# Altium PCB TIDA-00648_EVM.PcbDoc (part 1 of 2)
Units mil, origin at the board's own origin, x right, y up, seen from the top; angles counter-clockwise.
Board outline 2200 x 2000 mil, 4 copper layers (Component Side, Ground Plane, Power Plane, Solder Side), stack 55.6 mil thick; 91 components, 64 nets, 274 pads, 141 vias.
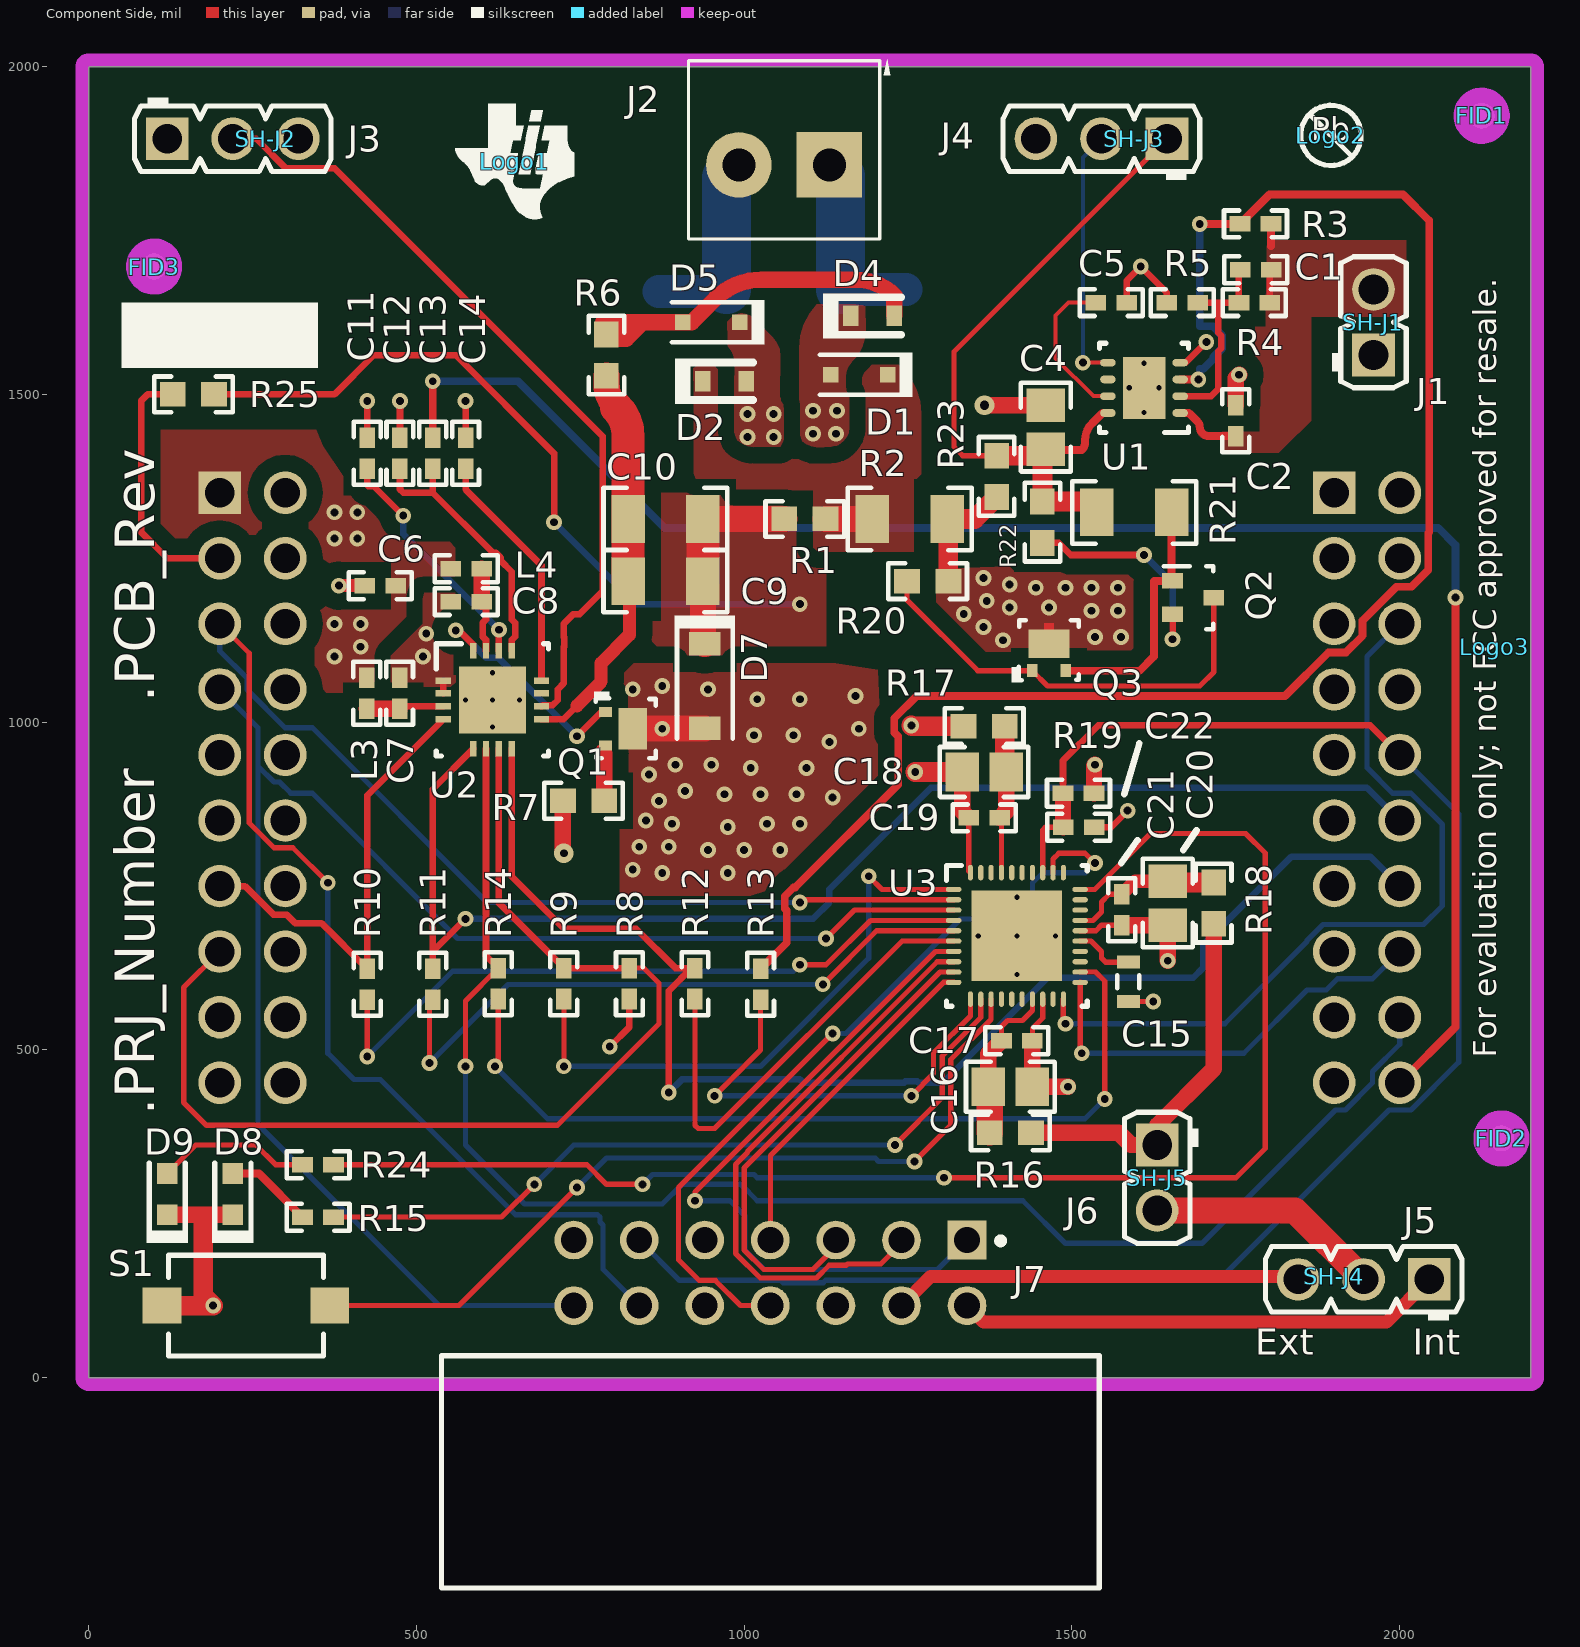
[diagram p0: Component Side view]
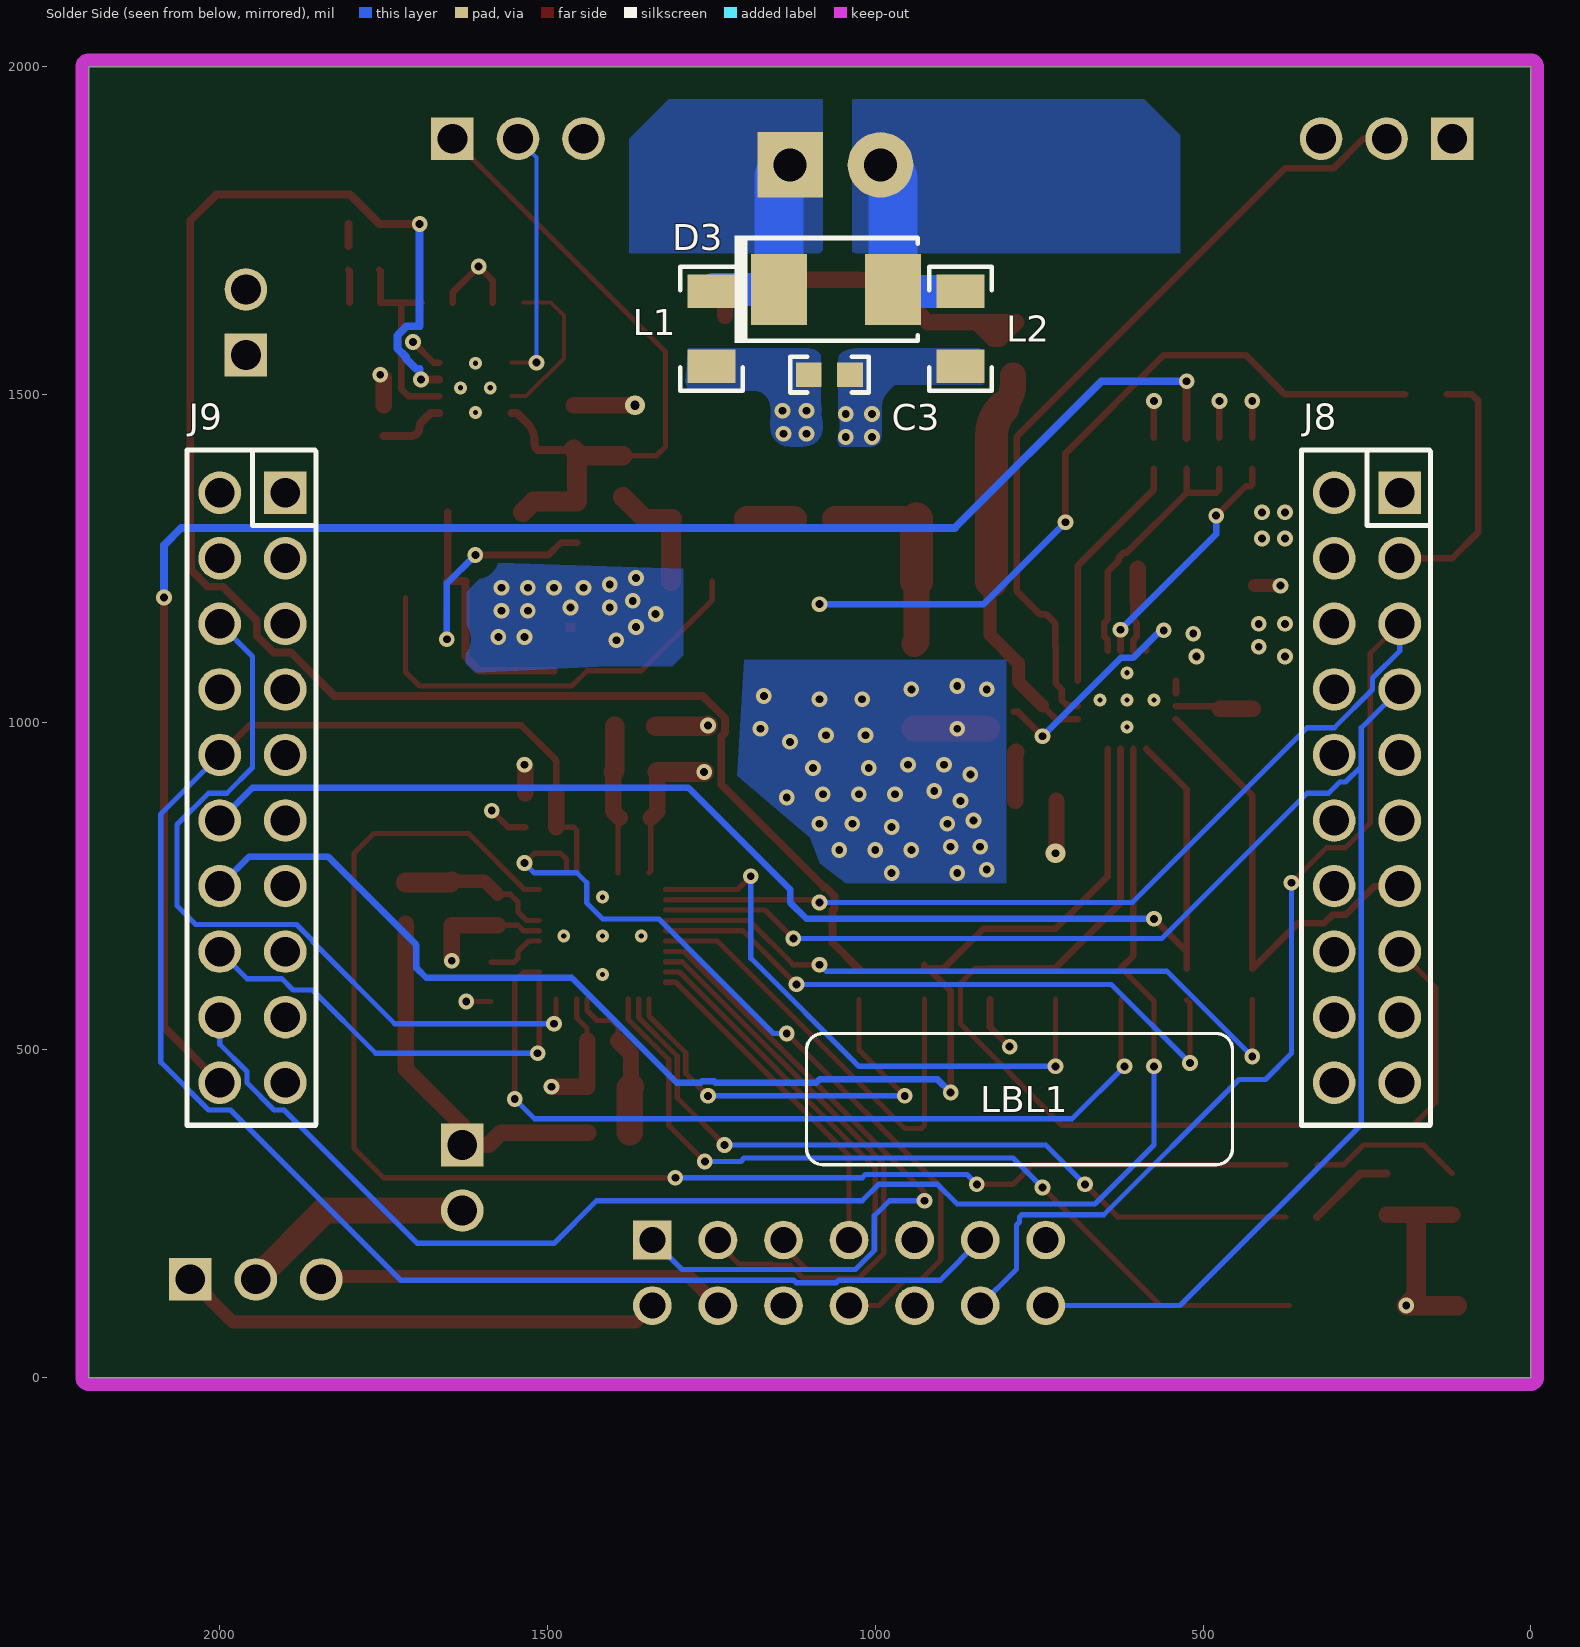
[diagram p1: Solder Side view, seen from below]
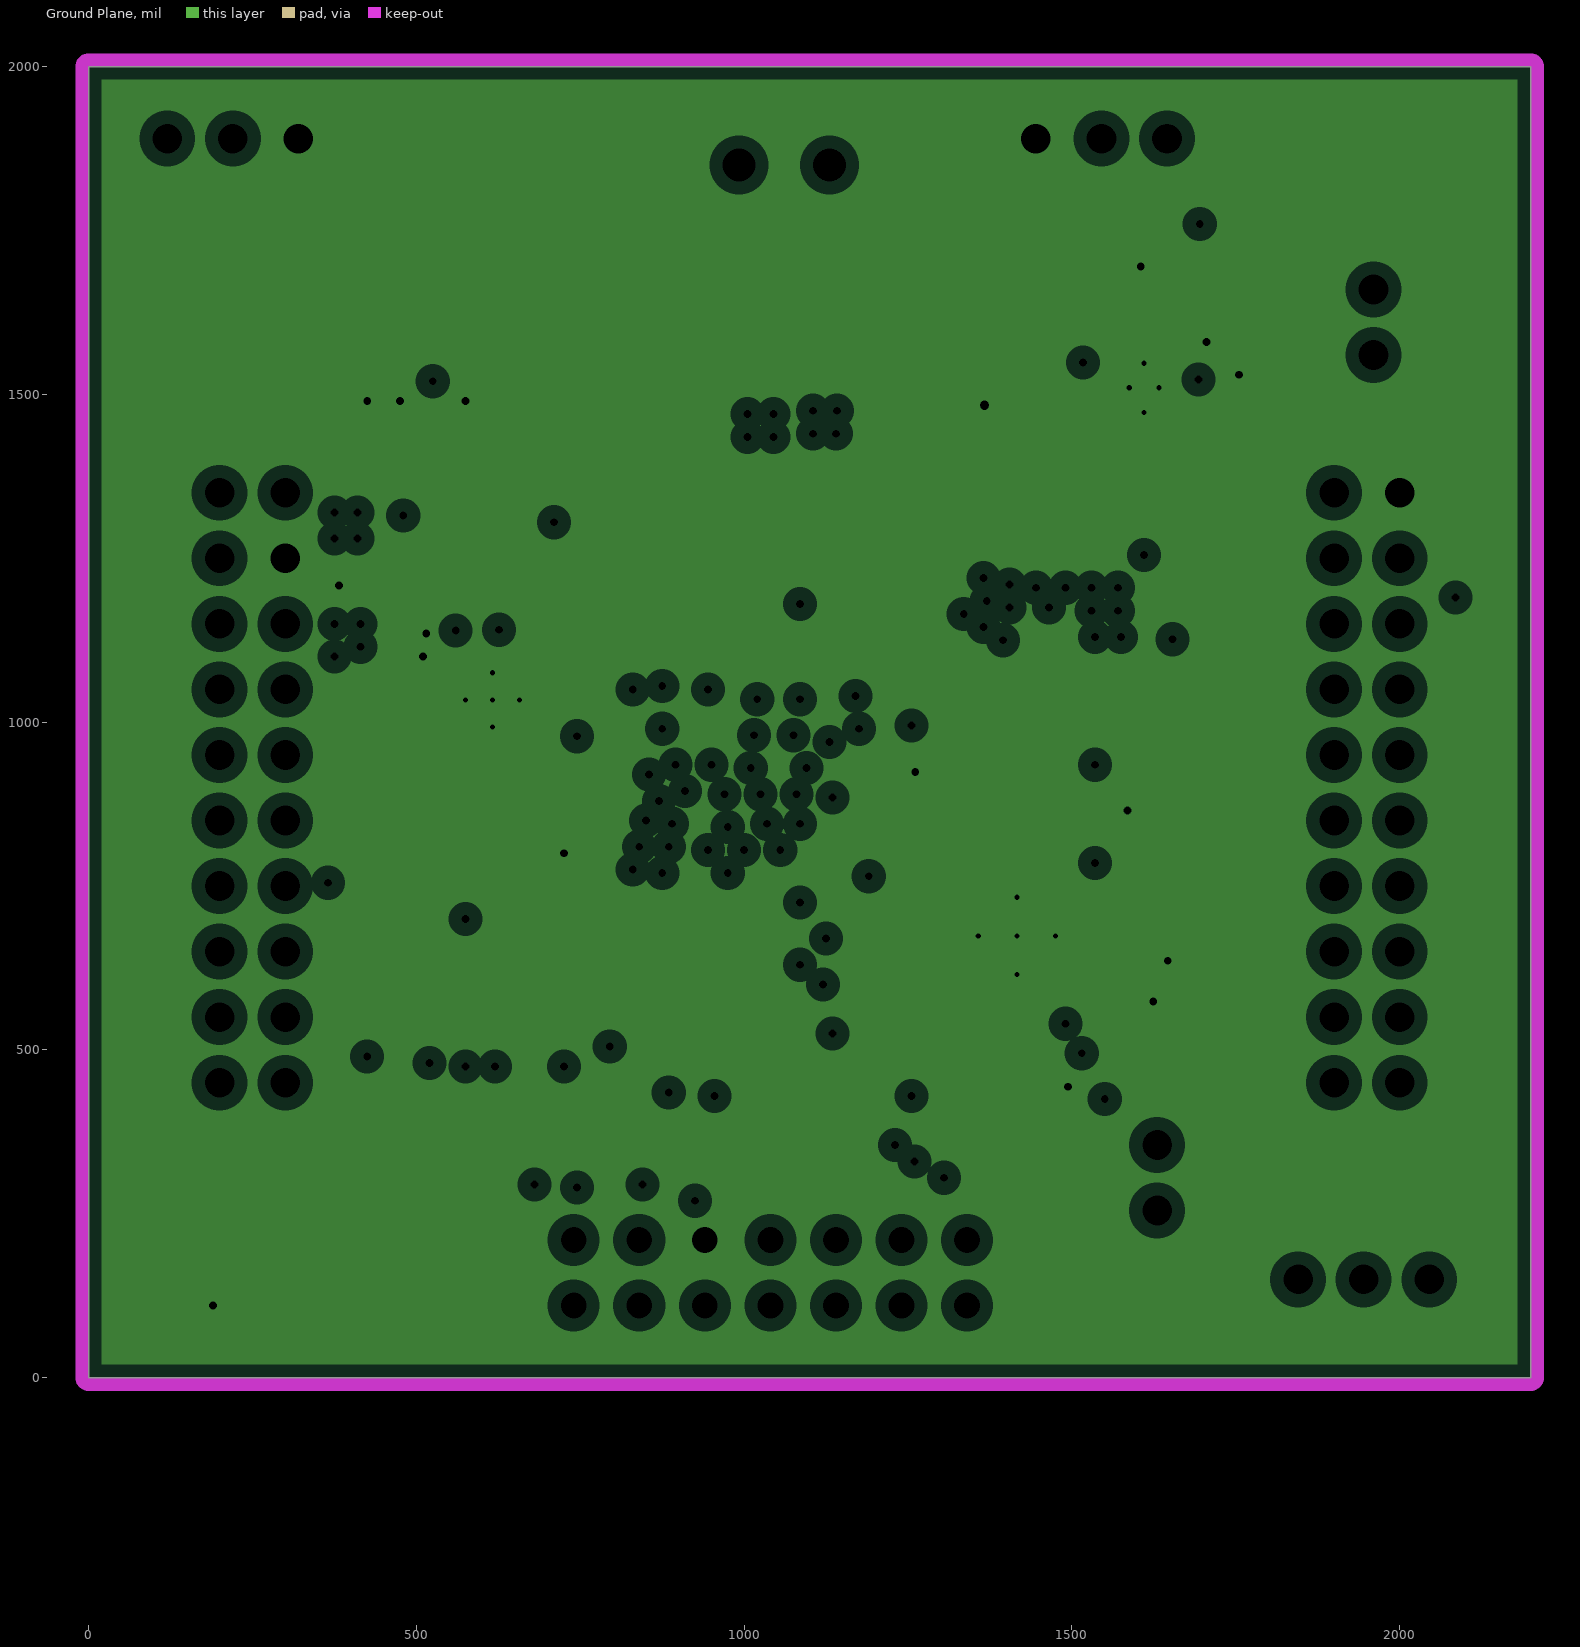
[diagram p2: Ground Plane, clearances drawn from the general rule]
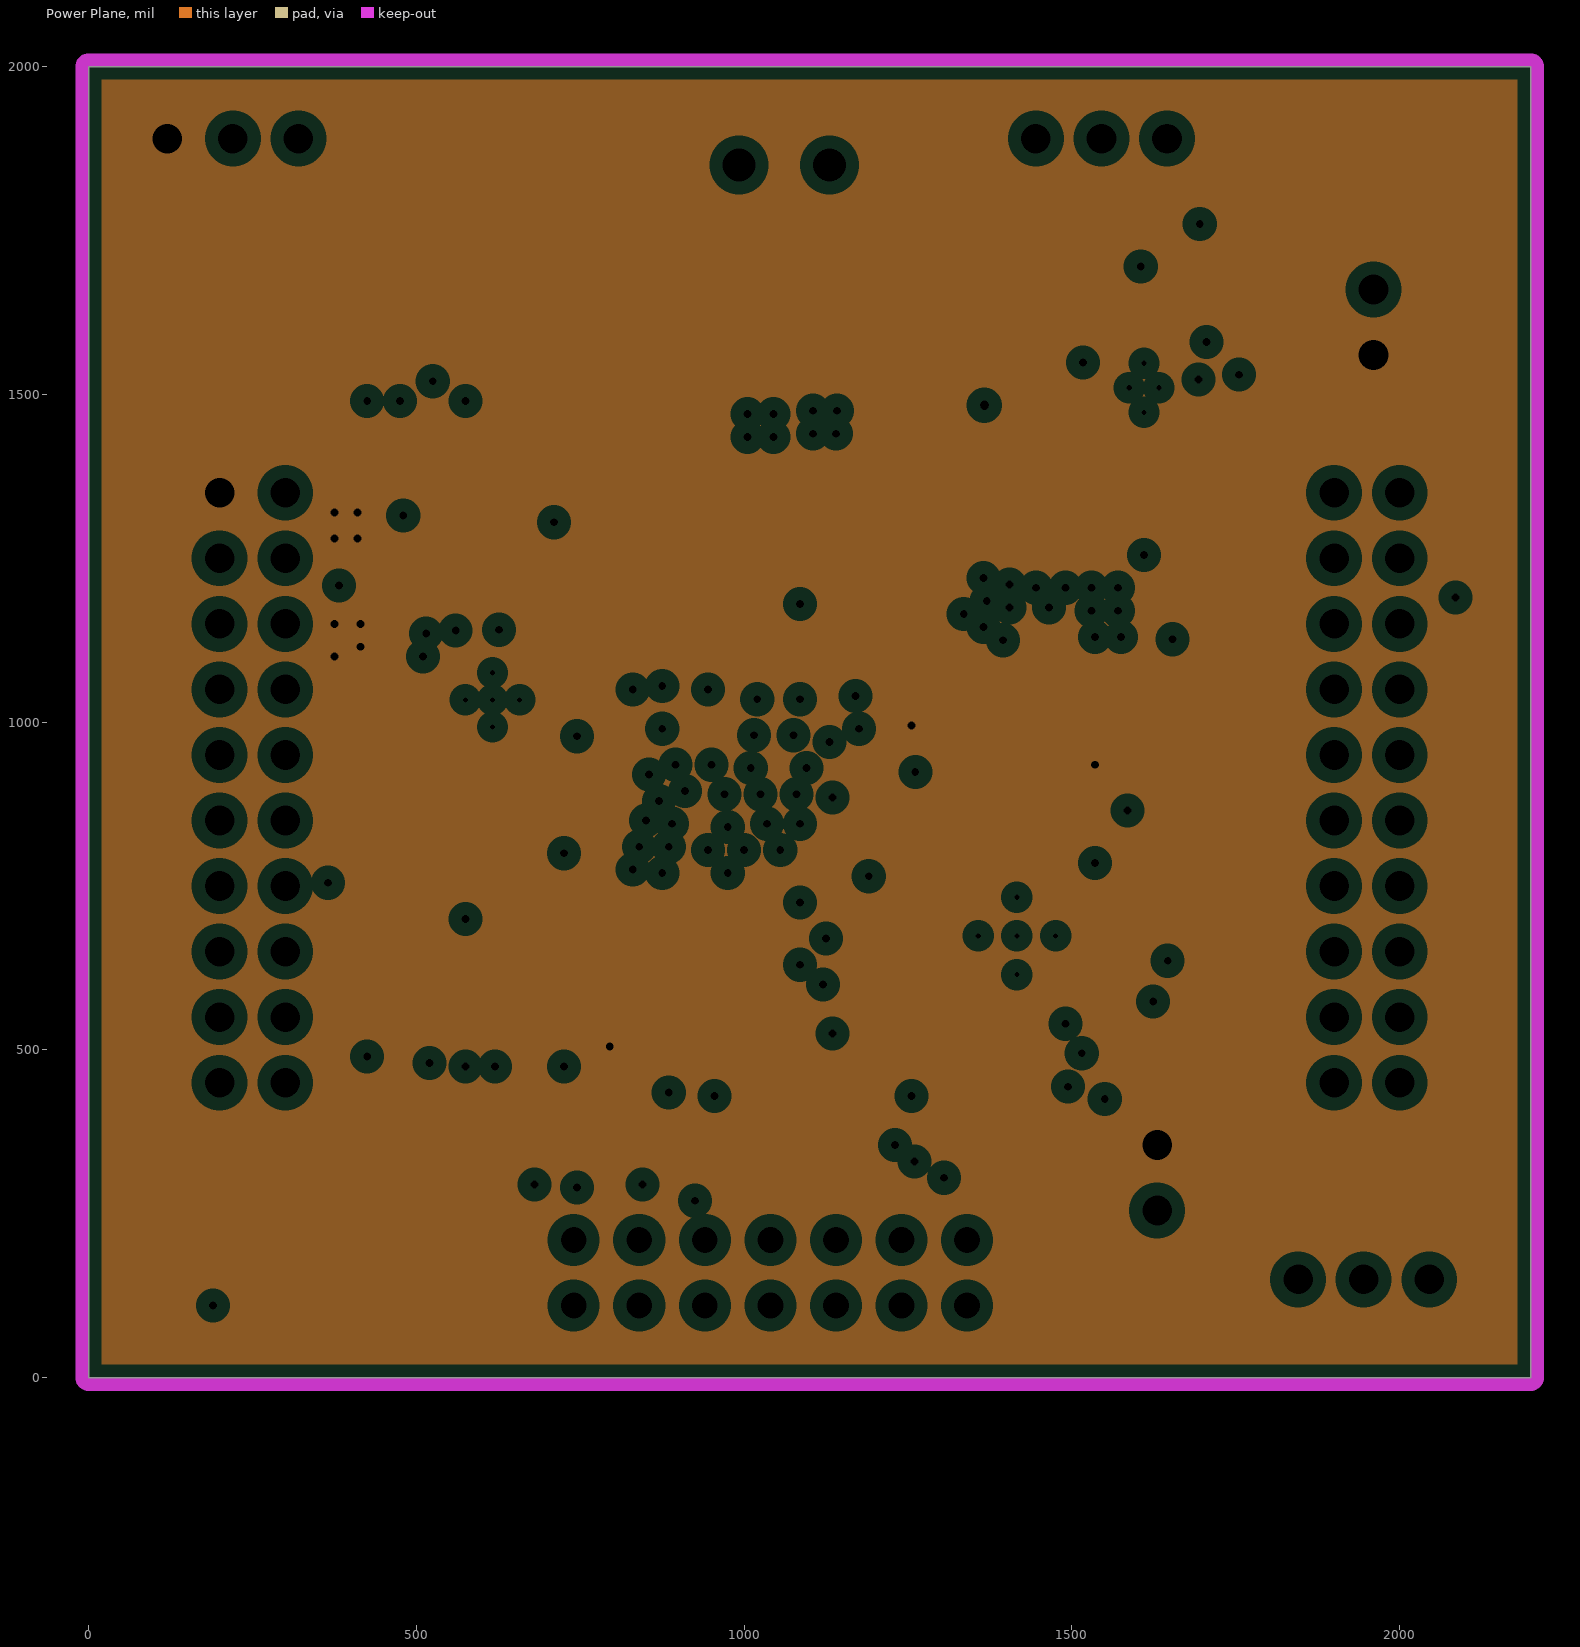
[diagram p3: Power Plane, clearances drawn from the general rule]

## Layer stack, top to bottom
Top Solder: solder mask 0.4, Solder Resist, Dk 3.5
Component Side: signal copper 1.4
Dielectric 1: core 10, FR-4, Dk 4.2
Ground Plane: plane copper 1.4, net GND
Dielectric 3: prepreg 30, FR-4, Dk 4.2
Power Plane: plane copper 1.4, net VCC
Dielectric 4: core 10, FR-4, Dk 4.2
Solder Side: signal copper 1.4
Bottom Solder: solder mask 0.4, Solder Resist, Dk 3.5

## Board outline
0,0 2200,0 2200,2000 0,2000

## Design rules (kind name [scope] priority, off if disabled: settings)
AcuteAngle [All] p1: minimum=4.50000000000000E+0001 checktracksonly=FALSE
AssemblyTestPointUsage [All] p1: valid=2
Clearance Clearance_Keepouts [((IsTrack Or IsArc) And Not InPoly) And IsFree and IsKeepOut vs ((IsTrack Or IsArc) And Not InPoly) And IsFree and IsKeepOut] p1: gap=0
Clearance Clearance_BoardEdge_MountingHoles [OnCopper and InComponentClass('Mounting Holes') vs IsKeepOut] p2: gap=40
Clearance Clearance_BoardEdge_Poly [OnCopper and InPoly vs IsKeepOut] p3: gap=25
Clearance Clearance_BoardEdge [OnCopper and Not InComponentClass('Logo') and not InComponentClass('FiducialMark') and not InRegion(1000,500,4000,800) and Not IsKeepout vs IsKeepOut] p4: gap=75
Clearance Clearance_Poly [InPolygon] p5: gap=25
Clearance [All] p6: gap=5
ComponentClearance ComponentClearance_MountingHoles_FiducialMarks [InComponentClass('Mounting Holes') vs InComponentClass('FiducialMark')] p1: gap=50 collisioncheckmode=3 verticalgap=10 showdistances=FALSE
ComponentClearance ComponentClearance_Shunt [InComponentClass('Header') vs InComponentClass('Shunt')] p2: gap=0 collisioncheckmode=3 verticalgap=0 showdistances=FALSE
ComponentClearance ComponentClearance_Logo [InComponentClass('Logo')] p3: gap=50 collisioncheckmode=3 verticalgap=10 showdistances=FALSE
ComponentClearance ComponentClearance_ScrewToNut [(HasFootprint('NY PMS 440 0025 PH')) vs (HasFootprint('Keystone_1902C'))] p4: gap=5 collisioncheckmode=3 verticalgap=10 showdistances=FALSE
ComponentClearance ComponentClearance_MountingHoles [InComponentClass('Mounting Holes')] p5: gap=250 collisioncheckmode=3 verticalgap=100000 showdistances=FALSE
ComponentClearance ComponentClearance_SmallPassives [HasFootprint('0201*') or HasFootprint('0402*') or HasFootprint('0508') or HasFootprint('0603*') or HasFootprint('0612') or HasFootprint('0805*') or HasFootprint('0815*') or HasFootprint('0830*') or HasFootprint('1206*') or HasFootprint('1210*') or HasFootprint('1808*') or HasFootprint('1812*') or HasFootprint('1825*') or HasFootprint('2010*') or HasFootprint('2220*') or HasFootprint('2225*') or HasFootprint('2512*') or HasFootprint('2728*') or HasFootprint('3518*') vs HasFootprint('0201*') or HasFootprint('0402*') or HasFootprint('0508') or HasFootprint('0603*') or HasFootprint('0612') or HasFootprint('0805*') or HasFootprint('0815*') or HasFootprint('0830*') or HasFootprint('1206*') or HasFootprint('1210*') or HasFootprint('1808*') or HasFootprint('1812*') or HasFootprint('1825*') or HasFootprint('2010*') or HasFootprint('2220*') or HasFootprint('2225*') or HasFootprint('2512*') or HasFootprint('2728*') or HasFootprint('3518*')] p6: gap=20 collisioncheckmode=3 verticalgap=10 showdistances=FALSE
ComponentClearance ComponentClearance_THtoSMT [IsThruComponent vs IsSMTComponent] p7: gap=100 collisioncheckmode=3 verticalgap=30 showdistances=FALSE
ComponentClearance ComponentClearance_THtoTH [IsThruComponent vs IsThruComponent] p8: gap=118.11 collisioncheckmode=3 verticalgap=30 showdistances=FALSE
ComponentClearance [All] p9: gap=40 collisioncheckmode=3 verticalgap=10 showdistances=FALSE
DiffPairsRouting [All] p1: maxlimit=100 minlimit=10 mostfreqgap=10 toplayer_minwidth=15 toplayer_maxwidth=15 toplayer_prefwidth=15 bottomlayer_minwidth=15 bottomlayer_maxwidth=15 bottomlayer_prefwidth=15 maxuncoupledlength=1000
FabricationTestPointUsage TestPointUsage [All] p1: valid=2 allowmultiple=FALSE
FabricationTestpoint Testpoint [All] p1: side=3 testpointundercomponent=TRUE minsize=40 maxsize=100 preferedsize=60 minholesize=0 maxholesize=40 preferedholesize=32 testpointgrid=1 allowsidetop=TRUE allowsidebottom=TRUE usegrid=TRUE gridtolerance=0.01
FanoutControl Fanout_LCC [IsLCC] p1: bgadir=Out bgaviamode=Centered fanoutstyle=Auto fanoutdirection=Alternating viagrid=1 // Fanout_LCC (Default Rule)
FanoutControl Fanout_BGA [IsBGA] p2: bgadir=Out bgaviamode=Centered fanoutstyle=Auto fanoutdirection=Alternating viagrid=1 // Fanout_BGA (Default Rule)
FanoutControl Fanout_Default [All] p4: bgadir=Out bgaviamode=Centered fanoutstyle=Auto fanoutdirection=Alternating viagrid=1 // Fanout_Default (Default Rule)
FanoutControl Fanout_Small [(CompPinCount < 5)] p5: bgadir=Out bgaviamode=Centered fanoutstyle=Auto fanoutdirection=OutThenIn viagrid=1 // Fanout_Small (Default Rule)
HoleSize [All] p1: absolutevalues=TRUE maxlimit=251 minlimit=7.87 maxpercent=80.000 minpercent=20.000
MinimumAnnularRing MinimumAnnularRing_ThermalPadVias [IsVia and InAnyComponent] p1: minimumring=5.91
MinimumAnnularRing [All] p2: minimumring=6
MinimumSolderMaskSliver MinimumSolderMaskSliver_Logo [InComponentClass('Logo') vs InComponentClass('Logo')] p1: minsoldermaskwidth=0.7
MinimumSolderMaskSliver [All] p2: minsoldermaskwidth=3.94
PlaneClearance [All] p1: clearance=20
PlaneConnect [All] p1: planeconnectstyle=Relief reliefexpansion=10 reliefentries=4 reliefconductorwidth=10 reliefairgap=10
PolygonConnect [All] p1: connectstyle=Direct reliefconductorwidth=10 reliefentries=4 polygonreliefangle="90 Angle" airgapwidth=10
RoutingVias ThermalPadVias [IsVia and InAnyComponent] p1: holewidth=8 width=20 viastyle="Through Hole" minholewidth=7.87 minwidth=19.68 maxholewidth=13 maxwidth=24
RoutingVias [All] p2: holewidth=12 width=24 viastyle="Through Hole" minholewidth=7.87 minwidth=24 maxholewidth=40 maxwidth=65
SMDNeckDown [All] p1: percent=160.000
SilkToBoardRegionClearance [Not ((IsComment or IsDesignator) And (Hide <> 'False')) and not InRegion(1000,500,4000,800)] p1 off:
SilkToSilkClearance SilkToSilkClearance_Pb-FreeLogo [(HasFootprint('Pb-Free_Overlay_Medium') OR HasFootprint('Pb-Free_Overlay_Small')) vs (HasFootprint('Pb-Free_Overlay_Medium') OR HasFootprint('Pb-Free_Overlay_Small'))] p1: silktosilkclearance=0
SilkToSilkClearance [All] p2: silktosilkclearance=4
SilkToSolderMaskClearance "Silk to Solder Mask Opening" [All] p1 off: minsilkscreentomaskgap=3 clearancetoexposedcopper=FALSE
SolderMaskExpansion [All] p1: expansion=1.97
UnpouredPolygon [All] p1: allowunpoured=FALSE
Width [All] p1: maxlimit=100 minlimit=6 preferedwidth=10 checkconnectedcopper=TRUE
13 further rules are at their usual default settings.

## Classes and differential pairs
component class Label: LBL1
component class AssemblyNote: ZZ1 ZZ2 ZZ3 ZZ4
component class FiducialMark: FID1 FID2 FID3
component class TIDA-00648_Hardware: FID1 FID2 FID3 LBL1 Logo1 Logo2 Logo3 ZZ1 ZZ2 ZZ3 ZZ4
component class Logo: Logo1
component class Header: J1 J3 J4 J5 J6
component class Shunt: SH-J1 SH-J2 SH-J3 SH-J4 SH-J5
component class TIDA-00648_DAC: C1 C2 C3 C4 C5 C6 C7 C8 C9 C10 C11 C12 C13 C14 D1 D2 D3 D4 D5 D7 J1 J2 J3 J4 L1 L2 L3 L4 Q1 Q2 Q3 R1 R2 R3 R4 R5 R6 R7 R8 R20 R21 R22 R23 SH-J1 SH-J2 SH-J3 U1 U2
component class TIDA-00648_MCU: C15 C16 C17 C18 C19 C20 C21 C22 D8 D9 J5 J6 J7 J8 J9 R9 R10 R11 R12 R13 R14 R15 R16 R17 R18 R19 R24 R25 S1 SH-J4 SH-J5 U3

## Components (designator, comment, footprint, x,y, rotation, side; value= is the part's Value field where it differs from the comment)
C1 "GRM155R61A103KA01D" 0402 1780.16,1690 r180 top
C2 "C1005X5R1C225K050BC" 0402 1750,1460 r90 top
C3 "C1608X7R2A103K" 0603 1070,1530 r180 bottom
C4 "GRM21BR72A474KA73L" 0805 1460,1450 r90 top
C5 "GRM155R61A104KA01D" 0402 1560,1640 r0 top
C6 "C1005X5R1C225K050BC" 0402 444.93,1208.24 r180 top
C7 "C1005X5R0J104K" 0402 474.41,1043.94 r90 top
C8 "C1005X5R0J104K" 0402 576.06,1183.94 r180 top
C9 "12061C104JAT2A" 1206 880,1215 r180 top
C10 "GRM31CR72A105KA01L" 1206 880,1310 r180 top
C11 "GRM155R61A394KE15D" 0402 425,1410 r90 top
C12 "GRM155R60J224KE01D" 0402 475,1410 r90 top
C13 "GRM155R71E682KA01D" 0402 525,1410 r90 top
C14 "GRM155R60J102KA01D" 0402 575,1410 r90 top
C15 "GRM188R70J474KA01D" 0603S 1586.06,603.94 r270 top
C16 "GRM21BR61C106KE15L" 0805 1406.06,443.94 r0 top
C17 "GRM155R71A104KA01D" 0402 1416.06,513.94 r180 top
C18 "GRM21BR61C106KE15L" 0805 1366.06,923.94 r180 top
C19 "GRM155R71A104KA01D" 0402 1366.06,853.94 r0 top
C20 "GRM21BR61C106KE15L" 0805 1646.06,723.94 r270 top
C21 "GRM155R71A104KA01D" 0402 1576.06,713.94 r90 top
C22 "GRM155R70J222KA01D" 0402 1510.19,839.84 r0 top
D1 "BAT46WJ,115" SOD-323F 1175.77,1529.66 r180 top
D2 "CDSU101A" SOD-523F 970,1520 r0 top
D3 "SM6T39CA" SMB 1060,1660 r180 bottom
D4 "CDSU101A" SOD-523F 1195.77,1619.66 r0 top
D5 "BAT46WJ,115" SOD-323F 950,1610 r180 top
D7 "MMSZ4686T1G" SOD-123 940,1055 r270 top
D8 "150060VS75000" WL-SMCW_GREEN 220,280 r90 top
D9 "150060SS75000" WL-SMCW_RED 120,280 r90 top
FID1 "Fiducial" Fiducial10-20 2125,1925 r0 top
FID2 "Fiducial" Fiducial10-20 2155,365 r0 top
FID3 "Fiducial" Fiducial10-20 100,1695 r0 top
J1 "61300211121" WURTH_61300211121 1960,1610 r90 top
J2 "ED555/2DS" TERM_BLK_ED555-2DS 1130,1850 r180 top
J3 "61300311121" WURTH_61300311121 220,1890 r0 top
J4 "61300311121" WURTH_61300311121 1545,1890 r180 top
J5 "61300311121" WURTH_61300311121 1945,150 r180 top
J6 "61300211121" WURTH_61300211121 1630,305 r270 top
J7 "SBH11-PBPC-D07-RA-BK" Sullins_SBH11-PBPC-D07-RA-BK 1040,160 r180 top
J8 "SSW-110-23-F-D" CONN_SSW-110-23-F-D 250,900 r90 bottom
J9 "SSW-110-23-F-D" CONN_SSW-110-23-F-D 1950,900 r90 bottom
L1 "MI1206K601R-10" 1206 1250,1600 r270 bottom
L2 "MI1206K601R-10" 1206 870,1600 r270 bottom
L3 "BLM15HG102SN1D" 0402 424.41,1043.94 r270 top
L4 "BLM15HG102SN1D" 0402 576.06,1233.94 r0 top
LBL1 "Size: 0.65\" x 0.20 \"" Label_650x200 780,425 r180 bottom
Logo1 "Texas Instruments" TI_Symbol_Overlay_Small 650,1855 r0 top
Logo2 "Pb-Free Symbol" Pb-Free_Overlay_Small 1895,1895 r0 top
Logo3 "FCC disclaimer" FCC_disclaimer 2145,1115 r90 top
Q1 "BC55-16PA,115" SOT1061 820,990 r0 top
Q2 "MMSTA06-7-F" SOT-323 1685,1190 r0 top
Q3 "BC55-16PA,115" SOT1061 1465,1110 r90 top
R1 "CRCW06030000Z0EA" 0603 1092.52,1310 r180 top
R2 "CRCW1206200RFKEA" 1206 1252.52,1310 r0 top
R3 "CRCW04021M00JNED" 0402 1780,1760 r0 top
R4 "CRCW04022M00FKED" 0402 1778.35,1640 r0 top
R5 "CRCW04021M13FKED" 0402 1668.35,1640 r0 top
R6 "CRCW06030000Z0EA" 0603 790,1560 r90 top
R7 "CRCW060320R0FKEA" 0603 755,880 r0 top
R8 "CRCW04021M00JNED" 0402 825,601.22 r90 top
R9 "CRCW04020000Z0ED" 0402 725,601.22 r270 top
R10 "CRCW04020000Z0ED" 0402 425,600 r270 top
R11 "CRCW04020000Z0ED" 0402 525,600 r270 top
R12 "CRCW04020000Z0ED" 0402 925,601.22 r270 top
R13 "CRCW04020000Z0ED" 0402 1025,600 r270 top
R14 "CRCW04020000Z0ED" 0402 625,601.22 r90 top
R15 "CRCW0402470RJNED" 0402 350,245 r0 top
R16 "CRCW060310R0FKEA" 0603 1406.06,373.94 r0 top
R17 "CRCW060310R0FKEA" 0603 1366.06,993.94 r180 top
R18 "CRCW060310R0FKEA" 0603 1716.06,723.94 r270 top
R19 "CRCW040247K0JNED" 0402 1510,891.65 r0 top
R20 "CRCW060324K9FKEA" 0603 1280,1215 r0 top
R21 "CRCW120649R9FKEA" 1206 1595,1320 r0 top
R22 "CRCW0603100RFKEA" 0603 1455,1305 r270 top
R23 "CRCW06030000Z0EA" 0603 1385,1375 r90 top
R24 "CRCW0402470RJNED" 0402 350,325 r0 top
R25 "CRCW06030000Z0EA" 0603 160,1500 r180 top
S1 "434121025816" SW_434121025816 240,110 r180 top
SH-J1 "969102-0000-DA" SNT-100-BK-G 1960,1610 r90 top
SH-J2 "969102-0000-DA" SNT-100-BK-G 270,1890 r180 top
SH-J3 "969102-0000-DA" SNT-100-BK-G 1595,1890 r180 top
SH-J4 "969102-0000-DA" SNT-100-BK-G 1900,155 r180 top
SH-J5 "969102-0000-DA" SNT-100-BK-G 1630,305 r90 top
U1 "TPS7A1601DRBR" DRB0008B 1610,1510 r180 top
U2 "DAC161S997RGHR" RGH0016A 616.06,1033.94 r0 top
U3 "MSP430F5172IRSBR" RSB0040B 1416.06,673.94 r0 top
ZZ1 "This Assembly Note is for PCB labels only" AssemblyNoteLabel 185,3938 r0 top
ZZ2 "This Assembly Note will show in the PcbDoc and associated outputs" AssemblyNote 185,3829.11 r0 top
ZZ3 "This Assembly Note will show in the PcbDoc and associated outputs" AssemblyNote 185,3740.56 r0 top
ZZ4 "This Assembly Note will show in the PcbDoc and associated outputs" AssemblyNote 185,3652 r0 top

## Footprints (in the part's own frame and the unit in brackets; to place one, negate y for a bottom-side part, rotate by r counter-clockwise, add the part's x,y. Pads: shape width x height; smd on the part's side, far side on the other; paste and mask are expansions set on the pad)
0402 [mm] "0402 from SM-752 data"
  rect 0.8x0.6 smd: 1(-0.6,0) 2(0.6,0)
  silkscreen extent -1.22,-0.52 1.22,0.52, body extent -0.55,-0.3 0.55,0.3, height 0.6
0603 [mm] "0603 from SM-752 data"
  rect 1x0.95 smd: 1(-0.8,0) 2(0.8,0)
  silkscreen extent -1.52,-0.69 1.52,0.69, body extent -0.87,-0.47 0.87,0.47, height 1
0603S [mil]
  rect 20x35 smd: 1(-30,0) 2(30,0)
  silkscreen extent -10,-17 10,17, body extent -34,-19 34,19, height 39
0805 [mm] "0805 from SM-752 data"
  rect 1.3x1.5 smd: 1(-0.85,0) 2(0.85,0)
  silkscreen extent -1.72,-0.97 1.72,0.97, body extent -1.1,-0.72 1.1,0.72, height 1.45
1206 [mm] "1206 from SM-752 data"
  rect 1.3x1.85 smd: 1(-1.45,0) 2(1.45,0)
  silkscreen extent -2.4,-1.21 2.4,1.21, body extent -1.7,-0.9 1.7,0.9, height 1.35
AssemblyNote [mil] "Assembly Note"
AssemblyNoteLabel [mil] "Assembly Note for PCB Labels"
CONN_SSW-110-23-F-D [mm] "SAMTEC"
  rect 1.65x1.65 hole 1.15: 1(11.43,-1.27)
  round 1.65 hole 1.15: 2(11.43,1.27) 3(8.89,-1.27) 4(8.89,1.27) 5(6.35,-1.27) 6(6.35,1.27) 7(3.81,-1.27) 8(3.81,1.27) 9(1.27,-1.27) 10(1.27,1.27) 11(-1.27,-1.27) 12(-1.27,1.27) 13(-3.81,-1.27) 14(-3.81,1.27) 15(-6.35,-1.27) 16(-6.35,1.27) 17(-8.89,-1.27) 18(-8.89,1.27) 19(-11.43,-1.27) 20(-11.43,1.27)
  silkscreen extent -13.08,-2.46 13.08,2.54, body extent -13,-2.51 13,2.54, height 8.59
DRB0008B [mm] "SON, 8-Leads, Body 3x3mm, Pitch 0.65mm, Thermal Pad 2.4x1.65mm, TI Recommended"
  oval 0.6x0.3 smd: 1(-1.4,0.975) 2(-1.4,0.325) 3(-1.4,-0.325) 4(-1.4,-0.975) 5(1.4,-0.975) 6(1.4,-0.325) 7(1.4,0.325) 8(1.4,0.975)
  rect 1.65x2.4 smd paste-1.2: 9(0,0)
  silkscreen extent -1.73,-1.73 1.73,1.73, body extent -1.57,-1.57 1.58,1.58, height 1.01
FCC_disclaimer [mil]
Fiducial10-20 [mm]
  round 1 smd mask+0.5: 1(0,0)
  Component Side keep-out circle w1.178: c0,0 r0.5
Label_650x200 [mil] "Thermal Transfer Label"
  round 1 on Mech14: 0(0,0)
  silkscreen extent -325,-100 325,100, body extent -326,-101 326,101, height 1
Pb-Free_Overlay_Small [mil]
  silkscreen extent -46,-46 46,46
RGH0016A [mm] "QFN, 16-Leads, Body 4x4mm, Pitch 0.5mm, TI Recommended"
  rect 0.6x0.25 smd: 1(-1.9,0.75) 2(-1.9,0.25) 3(-1.9,-0.25) 4(-1.9,-0.75) 9(1.9,-0.75) 10(1.9,-0.25) 11(1.9,0.25) 12(1.9,0.75)
  rect 0.25x0.6 smd: 5(-0.75,-1.9) 6(-0.25,-1.9) 7(0.25,-1.9) 8(0.75,-1.9) 13(0.75,1.9) 14(0.25,1.9) 15(-0.25,1.9) 16(-0.75,1.9)
  rect 2.6x2.6 smd paste-1.3: 17(0,0)
  silkscreen extent -2.17,-2.17 2.17,2.17, body extent -2.05,-2.05 2.05,2.05, height 0.81
RSB0040B [mm] "QFN, 40-Leads, Body 5x5mm, Pitch 0.4mm, Thermal Pad 3.5x3.5mm, TI Recommended"
  oval 0.6x0.2 smd: 1(-2.45,1.8) 2(-2.45,1.4) 3(-2.45,1) 4(-2.45,0.6) 5(-2.45,0.2) 6(-2.45,-0.2) 7(-2.45,-0.6) 8(-2.45,-1) 9(-2.45,-1.4) 10(-2.45,-1.8) 21(2.45,-1.8) 22(2.45,-1.4) 23(2.45,-1) 24(2.45,-0.6) 25(2.45,-0.2) 26(2.45,0.2) 27(2.45,0.6) 28(2.45,1) 29(2.45,1.4) 30(2.45,1.8)
  oval 0.2x0.6 smd: 11(-1.8,-2.45) 12(-1.4,-2.45) 13(-1,-2.45) 14(-0.6,-2.45) 15(-0.2,-2.45) 16(0.2,-2.45) 17(0.6,-2.45) 18(1,-2.45) 19(1.4,-2.45) 20(1.8,-2.45) 31(1.8,2.45) 32(1.4,2.45) 33(1,2.45) 34(0.6,2.45) 35(0.2,2.45) 36(-0.2,2.45) 37(-0.6,2.45) 38(-1,2.45) 39(-1.4,2.45) 40(-1.8,2.45)
  rect 3.5x3.5 smd paste-1.75: 41(0,0)
  silkscreen extent -2.72,-2.73 2.72,2.73, body extent -2.57,-2.57 2.58,2.58, height 0.81
SMB [mil] "Molded Diode, 2-Leads, Body 5.4x3.6mm, IPC Medium Density, based on OnSemi component dimensions"
  rect 85x107.99 smd: 1(-87.01,0) 2(87.01,0)
  silkscreen extent -155,-82 125,82, body extent -106,-71 106,71, height 91
SNT-100-BK-G [mil] "Samtec STEP model"
  round 1 on Mech3: 0(0,0)
  body extent -100,-50 100,50, height 344
SOD-123 [mm] "On Semi recommended land pattern"
  rect 0.915x1.22 smd: 1(-1.637,0) 2(1.637,0)
  silkscreen extent -2.74,-1.17 2.03,1.17, body extent -1.93,-0.9 1.93,0.9, height 1.35
SOD-323F [mm] "NXP recommended land pattern"
  rect 0.6x0.6 smd paste-0.05: 1(-1.1,0) 2(1.1,0)
  silkscreen extent -2.06,-0.86 1.53,0.86, body extent -1.35,-0.67 1.35,0.68, height 0.79
SOD-523F [mm] "COMCHIP"
  rect 0.6x0.8 smd paste-0.05: 1(-0.85,0) 2(0.85,0)
  silkscreen extent -1.92,-0.87 1.1,0.87, body extent -0.9,-0.5 0.9,0.5, height 0.85
SOT1061 [mm] "NXP SEMICONDUCTOR (HUSON3)"
  rect 0.5x0.4 smd mask+0.05: 1(-0.8,0.65) 2(-0.8,-0.65)
  rect 1.1x1.6 smd mask+0.05: 3(0.25,0)
  Component Side region: 1.05,-0.2 1.05,0.2 0.7,0.2 0.7,-0.2
  silkscreen extent -1.25,-1.15 1.15,1.45, body extent -1.05,-1.05 1.05,1.05, height 0.66
SOT-323 [mm] "Zetex recommended land pattern.  March 2007"
  rect 0.8x0.6 smd: 1(-0.8,0.65) 2(-0.8,-0.65) 3(0.8,0)
  silkscreen extent -1.14,-1.22 0.77,1.22, body extent -1.13,-1.13 1.12,1.12, height 1.13
Sullins_SBH11-PBPC-D07-RA-BK [mm] "Header (Shrouded), 2.54 mm, 7x2, R/A, TH"
  rect 1.5x1.5 hole 1: 1(-7.62,-1.27)
  round 1.5 hole 1: 2(-7.62,1.27) 3(-5.08,-1.27) 4(-5.08,1.27) 5(-2.54,-1.27) 6(-2.54,1.27) 7(0,-1.27) 8(0,1.27) 9(2.54,-1.27) 10(2.54,1.27) 11(5.08,-1.27) 12(5.08,1.27) 13(7.62,-1.27) 14(7.62,1.27)
  silkscreen extent -12.74,-1.36 12.74,12.21, body extent -12.74,-1.56 12.74,12.21, height 9.3
SW_434121025816 [mm] "SMD, 2-Leads, Body 6x3.9mm, Pitch 6.5mm"
  rect 1.5x1.4 smd: 1(-3.25,0) 2(3.25,0)
  silkscreen extent -3,-1.95 3,1.95, body extent -3.65,-1.95 3.65,1.95, height 2.5
TERM_BLK_ED555-2DS [mil]
  rect 100x100 hole 50: 1(0,0)
  round 100 hole 50: 2(138,0)
  silkscreen extent -93,-161 215,113, body extent -69,-150 207,106, height 323
TI_Symbol_Overlay_Small [mil]
  silkscreen extent -90,-88 91,88
WL-SMCW_GREEN [mm] "WURTH"
  rect 0.8x0.8 smd: 1(-0.8,0) 2(0.8,0)
  silkscreen extent -1.9,-0.8 1.2,0.8, body extent -0.85,-0.45 0.85,0.45, height 0.8
WL-SMCW_RED [mm] "WURTH"
  rect 0.8x0.8 smd: 1(-0.8,0) 2(0.8,0)
  silkscreen extent -1.9,-0.8 1.2,0.8, body extent -0.85,-0.45 0.85,0.45, height 0.8
WURTH_61300211121 [mm] "Header, 2.54mm, 2x1, TH"
  rect 1.65x1.65 hole 1.15: 1(-1.27,0)
  round 1.65 hole 1.15: 2(1.27,0)
  silkscreen extent -2.54,-1.27 2.54,1.6, body extent -2.54,-1.27 2.54,1.27, height 8.54
WURTH_61300311121 [mm] "Header, 2.54mm, 3x1, TH"
  rect 1.65x1.65 hole 1.15: 1(-2.54,0)
  round 1.65 hole 1.15: 2(0,0) 3(2.54,0)
  silkscreen extent -3.81,-1.27 3.81,1.6, body extent -3.81,-1.27 3.81,1.27, height 8.54

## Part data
C1: "CAP, CERM, 0.01 µF, 10 V, +/- 10%, X5R, 0402"
C2 C6: "CAP, CERM, 2.2 µF, 16 V, +/- 10%, X5R, 0402"
C3: "CAP, CERM, 0.01 µF, 100 V, +/- 10%, X7R, 0603"
C4: "CAP, CERM, 0.47 µF, 100 V, +/- 10%, X7R, 0805"
C5: "CAP, CERM, 0.1 µF, 10 V, +/- 10%, X5R, 0402"
C7 C8: "CAP, CERM, 0.1 µF, 6.3 V, +/- 10%, X5R, 0402"
C9: "CAP, CERM, 0.1 µF, 100 V, +/- 5%, X7R, 1206"
C10: "CAP, CERM, 1 µF, 100 V, +/- 10%, X7R, 1206"
C11: "CAP, CERM, 0.39 µF, 10 V, +/- 10%, X5R, 0402"
C12: "CAP, CERM, 0.22 µF, 6.3 V, +/- 10%, X5R, 0402"
C13: "CAP, CERM, 6800 pF, 25 V, +/- 10%, X7R, 0402"
C14: "CAP, CERM, 1000 pF, 6.3 V, +/- 10%, X5R, 0402"
C15: "CAP, CERM, 0.47 µF, 6.3 V, +/- 10%, X7R, 0603"
C16 C18 C20: "CAP, CERM, 10 µF, 16 V, +/- 10%, X5R, 0805"
C17 C19 C21: "CAP, CERM, 0.1 µF, 10 V, +/- 10%, X7R, 0402"
C22: "CAP, CERM, 2200 pF, 6.3 V, +/- 10%, X7R, 0402"
D1 D5: "Diode, Schottky, 100 V, 0.25 A, SOD-323F"
D2 D4: "Diode, Switching, 90 V, 0.1 A, SOD-523F"
D3: "Diode, TVS, Bi, 39 V, 600 W, SMB"
D7: "Diode, Zener, 3.9 V, 500 mW, SOD-123"
D8: "LED, Green, SMD"
D9: "LED, Super Red, SMD"
FID1 FID2 FID3: "Fiducial mark.  There is nothing to buy or mount."
J1 J6: "Header, 2.54 mm, 2x1, Gold, TH"
J2: "Terminal Block, 6A, 3.5mm Pitch, 2-Pos, TH"
J3 J4 J5: "Header, 2.54 mm, 3x1, Gold, TH"
J7: "Header (Shrouded), 2.54 mm, 7x2, Gold, R/A, TH"
J8 J9: "Connector, Receptacle, 100mil, 10x2, Gold plated, TH"
L1 L2: "Ferrite Bead, 600 ohm @ 100 MHz, 1.5 A, 1206"
L3 L4: "Ferrite Bead, 1000 ohm @ 100 MHz, 0.25 A, 0402"
LBL1: library part THT-14-423-10, "Thermal Transfer Printable Labels, 0.650\" W x 0.200\" H - 10,000 per roll"
Logo1: library part TI_Logo, "Texas Instrument Corporate Signature"
Logo2: library part Pb-Free
Logo3: library part FCC_disclaimer, "FCC_disclaimer"
Q1 Q3: library part "BC55-16PA,115, NXP Semiconductor", "Transistor, NPN, 60 V, 1 A, AEC-Q101, SOT1061"
Q2: library part "MMSTA06-7-F, Diodes Inc.", "Transistor, NPN, 80 V, 0.5 A, SOT-323"
R1 R6 R23 R25: "RES, 0, 5%, 0.1 W, 0603"
R2: "RES, 200, 1%, 0.25 W, 1206"
R3 R8: "RES, 1.0 M, 5%, 0.063 W, 0402"
R4: "RES, 2.00 M, 1%, 0.063 W, 0402"
R5: "RES, 1.13 M, 1%, 0.063 W, 0402"
R7: "RES, 20.0, 1%, 0.1 W, 0603"
R9 R10 R11 R12 R13 R14: "RES, 0, 5%, 0.063 W, 0402"
R15 R24: "RES, 470, 5%, 0.063 W, 0402"
R16 R17 R18: "RES, 10.0, 1%, 0.1 W, 0603"
R19: "RES, 47 k, 5%, 0.063 W, 0402"
R20: "RES, 24.9 k, 1%, 0.1 W, 0603"
R21: "RES, 49.9, 1%, 0.25 W, 1206"
R22: "RES, 100, 1%, 0.1 W, 0603"
S1: "Switch, Tactile, SPST, 12 V, SMD"
SH-J1 SH-J2 SH-J3 SH-J4 SH-J5: "Shunt, 100mil, Gold plated, Black"
U1: "60-V, 5-µA IQ, 100-mA, Low-Dropout Voltage Regulator with Enable and Power-Good, DRB0008B"
U2: "16-bit SPI Programmable DAC for 4-20mA Loops, RGH0016A"
U3: "25 MHz Mixed Signal Microcontroller with 32 KB Flash, 2048 B SRAM and 29 GPIOs, -40 to 85 degC, 40-pin QFN (RSB), Green (RoHS & no Sb/Br)"
ZZ1: library part AssemblyNoteLabel
ZZ2 ZZ3 ZZ4: library part AssemblyNote

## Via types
v1: diameter 24, hole 12, Component Side to Solder Side, 125 vias
v2: diameter 19.68, hole 7.87, Component Side to Solder Side, 14 vias
v3: diameter 30, hole 14, Component Side to Solder Side, 1 vias
v4: diameter 30, hole 12, Component Side to Solder Side, 1 vias

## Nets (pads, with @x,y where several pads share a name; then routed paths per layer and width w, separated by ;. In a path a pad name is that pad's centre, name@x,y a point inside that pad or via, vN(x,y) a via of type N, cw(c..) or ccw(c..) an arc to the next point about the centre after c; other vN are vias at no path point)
EN: J4.2 U1.5 | length 391.6
  Component Side w6: v1(1516.61,1548.39) U1.5@1554.88,1548.39
  Solder Side w6: v1(1516.61,1548.39) 1516.61,1861.61 J4.2@1545,1890
ERRLVL: J3.2 U2.10 | length 1218.2
  Component Side w10: J3.2@220,1890 255.86,1890 301.21,1844.65 375.35,1844.65 784.3,1435.7 784.3,1424.91 784.45,1424.76 784.45,1200 749.32,1164.87 739.7,1164.87 725.13,1150.3 725.13,1129.7 725.39,1129.43 725.39,1114.68 724.57,1114.68 724.57,1059.02 715.55,1050 715.55,1033.53 708.01,1025.98 692.76,1025.98 U2.10@690.87,1024.09
GND: C2.2 C4.2 C5.2 C6.2 C7.2 C8.2 C11.2 C12.2 C14.2 C15.2 C16.2 C17.1 C18.2 C19.1 C20.2 C21.1 C22.2 D8.1 D9.1 J3.3 J4.3 J7.9 J8.4 J9.2 R5.1 R7.1 S1.2 U1.4 U1.9 U2.1 U2.2 U2.17 U3.18 U3.26 U3.40 U3.41 | length 1669.2
  Component Side w8: C19.1@1342.44,853.94 1342.44,773.15 U3.40@1345.2,770.39 ; C17.1@1439.69,513.94 1439.69,533.06 1455.43,548.81 U3.18@1455.43,577.48 ; U3.26@1512.52,681.81 1536.81,681.81 1545.31,690.31 C21.1@1576.06,690.31 ; C15.2@1586.06,573.94 v1(1623.94,573.94)
  Component Side w10: C11.2@425,1433.62 v1(425,1490) ; C12.2@475,1433.62 v1(475,1490) ; U2.2@541.26,1043.78 U2.1@541.26,1063.46 ; C14.2@575,1433.62 v1(575,1490) ; C22.2@1533.81,839.84 1559.84,839.84 v1(1585,865) ; C5.2@1583.62,1640 1583.62,1673.62 v1(1605,1695) 1644.72,1655.28 R5.1@1644.72,1640 ; U1.4@1665.12,1548.39 1673.39,1548.39 v1(1705,1580)
  Component Side w20: v1(381.76,1208.24) C6.2@421.31,1208.24
  Component Side w25: D9.1@120,248.5 D8.1@220,248.5 ; R7.1@723.5,880 723.5,801.5 v4(725,800) ; C18.2@1332.6,923.94 1332.6,863.78 C19.1@1342.44,853.94 ; v3(1366.54,1483.46) C4.2@1460,1483.46 ; C17.1@1439.69,513.94 1439.53,513.78 C16.2@1439.53,443.94 v1(1493.94,443.94) ; C21.1@1576.06,690.31 1645.91,690.31 C20.2@1646.06,690.47 v1(1646.06,636.06) ; C2.2@1750,1483.62 1750,1525 v1(1755,1530)
  Component Side w30: S1.2@112.05,110 v1(190,110) 175,125 175,235 ; v1(1261.06,923.94) C18.2@1332.6,923.94
  Solder Side w10: v1(1585,865) v1@1590,865
  other v1: 510,1100 515,1135
  other v2: 1416.06,614.88 1357.01,673.94 1416.06,673.94 1475.12,673.94 1416.06,732.99 616.06,992.6 574.72,1033.94 616.06,1033.94 657.4,1033.94 616.06,1075.28 1610,1472.6 1587.36,1510 1632.64,1510 1610,1547.4
HART_TX: C13.2 J9.20 | length 2605.1
  Component Side w12: C13.2@525,1433.62 v1(525,1520) ; J9.20@2000,450 2085,535 v1(2085,1190)
  Solder Side w12: v1(525,1520) 655,1520 878.65,1296.35 2058.65,1296.35 2085,1270 v1(2085,1190)
LOOP_M: C9.2 C10.2 R6.1 U2.9 | length 609
  Component Side w10: U2.9@690.87,1004.41 724.41,1004.41 745,1025
  Component Side w20: 745,1025 781.73,1061.73 781.73,1090 825,1133.27 825,1212.91 C9.2@822.91,1215
  Component Side w40: R6.1@790,1528.5 790,1516.21 ccw(c841.21,1516.21) 805,1480
  Component Side w50: 805,1480 cw(c761.75,1436.75) 822.91,1436.75 C10.2@822.91,1310 C9.2@822.91,1215
LOOP_P: C9.1 C10.1 D7.1 R1.2 R25.1 | length 1452.5
  Component Side w10: R25.1@191.5,1500 375,1500 435,1560 560,1560 710,1410 v1(710,1305)
  Component Side w40: C9.1@937.09,1215 937.09,1126.5 ccw(c947.03,1126.5) D7.1@940,1119.47 ; C10.1@937.09,1310 R1.2@1061.02,1310
  Component Side w50: C9.1@937.09,1215 C10.1@937.09,1310
  Solder Side w10: v1(710,1305) 835,1180 v1(1085,1180)
NDAC_ERROR: J8.15 R8.2 R9.1 U2.7 | length 1648.1
  Component Side w8: J8.15@200,650 145,595 145,420 180,385 715,385 870,540 870,601.72 846.88,624.84 R8.2@825,624.84
  Component Side w10: U2.7@625.91,959.13 625.91,723.94 R9.1@725,624.84 R8.2@825,624.84
NetC1_1: C1.1 C2.1 J1.2 R3.2 R4.2 U1.1 | length 188.2
  Component Side w10: R4.2@1801.97,1640 1801.97,1688.19 C1.1@1803.78,1690
  Component Side w12: U1.1@1665.12,1471.61 1676.1,1471.61 cw(c1676.1,1466.1) 1680,1470 1691.46,1458.54 cw(c1682.93,1450) 1695,1450 ccw(c1708.62,1450) 1708.62,1436.38 C2.1@1750,1436.38 ; 1803.62,1726.38 R3.2@1803.62,1760
NetC1_2: C1.2 R4.1 R5.2 U1.2 | length 311.9
  Component Side w10: U1.2@1665.12,1497.2 1712.2,1497.2 1723.35,1508.35 1723.35,1565.82 1728,1570.47 1728,1589.53 1723.35,1594.18 1723.35,1640 ; R5.2@1691.97,1640 1723.35,1640 ; C1.2@1756.54,1690 1754.72,1688.19 R4.1@1754.72,1640 1723.35,1640
NetC3_1: C3.1 D1.2 D4.1 L1.2
  other v1: 1105,1440 1140,1440 1105,1475 1141.68,1474.99
NetC3_2: C3.2 D2.2 D5.1 L2.2
  other v1: 1005,1435 1045,1435 1005,1470 1045,1470
NetC4_1: C4.1 J4.1 R21.1 R22.1 R23.2 U1.8 | length 1047.1
  Component Side w8: R23.2@1385,1406.5 1333.5,1406.5 1320,1420 1320,1565 J4.1@1645,1890
  Component Side w12: C4.1@1460,1416.54 ccw(c1463.71,1420.24) 1463.71,1415 1515,1415 ccw(c1502.93,1427.07) 1520,1427.07 1520,1430 cw(c1556.21,1430) 1530.61,1455.61 1545,1470 cw(c1548.9,1466.1) 1548.9,1471.61 U1.8@1554.88,1471.61
  Component Side w30: R23.2@1385,1406.5 C4.1@1449.96,1406.5 ; C4.1@1460,1416.54 C4.1@1449.96,1406.5 ; R21.1@1537.91,1320 1521.42,1336.5 R22.1@1455,1336.5 1455,1401.46 C4.1@1449.96,1406.5
NetC5_1: C5.1 U1.7 | length 238.5
  Component Side w6: C5.1@1536.38,1640 1495,1640 1475,1620 1475,1555 1532.8,1497.2 U1.7@1554.88,1497.2
NetC7_1: C7.1 L3.2 U2.3 | length 118.4
  Component Side w10: C7.1@474.41,1020.31 478.19,1024.09 U2.3@541.26,1024.09
  Component Side w25: L3.2@424.41,1020.31 C7.1@474.41,1020.31
NetC8_1: C8.1 L4.2 U2.15 | length 132.2
  Component Side w10: C8.1@599.68,1183.94 606.22,1177.4 606.22,1156.4 601.03,1151.21 601.03,1130.6 606.22,1125.41 U2.15@606.22,1108.74
  Component Side w25: C8.1@599.68,1183.94 L4.2@599.69,1233.94
NetC11_1: C11.1 U2.14 | length 365.5
  Component Side w10: C11.1@425,1386.38 425,1362 427,1360 435,1360 v1(480,1315) ; U2.14@625.91,1108.74 v1(625.91,1140.91)
  Solder Side w10: v1(480,1315) 480,1286.81 v1(625.91,1140.91)
NetC12_1: C12.1 C13.1 U2.13 | length 417.9
  Component Side w10: C12.1@475,1386.38 475,1355 480,1350 525,1350 ; C13.1@525,1386.38 525,1350 ; U2.13@645.59,1108.74 645.59,1125.41 650.78,1130.6 650.78,1151.21 645.59,1156.4 645.59,1229.41 628.31,1246.69 628.31,1251.08 620.77,1258.62 616.38,1258.62 525,1350
NetC14_1: C14.1 U2.12 | length 370.9
  Component Side w10: C14.1@575,1386.38 575,1355 690.87,1239.13 U2.12@690.87,1063.46
NetC15_1: C15.1 U3.25 | length 92.7
  Component Side w8: U3.25@1512.52,666.06 1528.94,666.06 1545,650 1545,640 1551.06,633.94 C15.1@1586.06,633.94
NetC16_1: C16.1 C17.2 R16.1 U3.17 | length 245.5
  Component Side w8: C17.2@1392.44,513.94 1392.44,535.81 1401.63,545 1424.37,545 1439.69,560.31 U3.17@1439.69,577.48
  Component Side w25: C16.1@1372.6,443.94 1372.6,494.09 C17.2@1392.44,513.94
  Component Side w40: C16.1@1372.6,443.94 1374.57,441.97 R16.1@1374.57,373.94
NetC18_1: C18.1 C19.2 R17.1 U3.37 | length 229.6
  Component Side w8: C19.2@1389.68,853.94 1392.44,851.18 U3.37@1392.44,770.39
  Component Side w25: C19.2@1389.68,853.94 1399.53,863.78 C18.1@1399.53,923.94
  Component Side w30: R17.1@1397.56,993.94 1397.56,925.91 C18.1@1399.53,923.94
NetC20_1: C20.1 C21.2 R18.1 U3.27 | length 237.9
  Component Side w8: U3.27@1512.52,697.56 1531.97,697.56 1545,710.59 1545,725.59 1556.97,737.56 C21.2@1576.06,737.56
  Component Side w20: C21.2@1576.06,737.56 1595.91,757.4 C20.1@1646.06,757.4
  Component Side w30: C20.1@1646.06,757.4 1648.03,755.43 R18.1@1716.06,755.43
NetD1_1: D1.1 D2.1 R1.1 R2.1 | length 71.4
  Component Side w40: R1.1@1124.02,1310 R2.1@1195.43,1310
NetD3_1: D3.1 J2.1 L1.1 | length 297.1
  Solder Side w50: D3.1@1147.01,1660 L1.1@1247.09,1660
  Solder Side w75: J2.1@1130,1850 1147.01,1832.99 D3.1@1147.01,1660
NetD3_2: D3.2 J2.2 L2.1 | length 302.1
  Solder Side w50: L2.1@870,1657.09 970.08,1657.09 D3.2@972.99,1660
  Solder Side w75: D3.2@972.99,1660 972.99,1830.99 J2.2@992,1850
NetD4_2: D4.2 D5.2 R6.2 | length 585.6
  Component Side w25: D4.2@1229.23,1619.66 1229.23,1648.15 cw(c1231.85,1648.15) 1230,1650 ccw(c1169.64,1589.64) 1169.64,1675 1026.42,1675 ccw(c1026.42,1575) 955.71,1645.71 920,1610 D5.2@906.69,1610 845,1610 ; 845,1610 820,1585 809.98,1585 784.98,1610 845,1610
NetD7_2: D7.2 Q1.3 | length 110.3
  Component Side w40: Q1.3@829.84,990 cw(c831.13,988.72) 831.13,990.53 D7.2@940,990.53
  other v1: 875,770 975,770 830,775 945,805 1000,805 1055,805 840,810 885,810 975,840 890,845 1035,845 1085,845 850,850 870,880 1135,885 970,890 1025,890 1080,890 910,895 855,920 1010,930 1095,930 895,935 950,935 1130,970 1015,980 1075,980 875,990 1175,990 1020,1035 1085,1035 1170,1040 830,1050 945,1050 875,1055
NetD8_2: D8.2 R15.1 | length 133.9
  Component Side w12: D8.2@220,311.5 259.88,311.5 R15.1@326.38,245
NetD9_2: D9.2 R24.1 | length 236.8
  Component Side w8: D9.2@120,311.5 163.5,355 255,355 285,325 R24.1@326.38,325
NetJ5_2: J5.2 J6.2 | length 358.5
  Component Side w40: J6.2@1630,255 1840,255 J5.2@1945,150
NetJ8_3: J8.3 R25.2 | length 389.2
  Component Side w10: R25.2@128.5,1500 90,1500 80,1490 80,1290 120,1250 J8.3@200,1250
NetQ1_1: Q1.1 U2.16 | length 360.7
  Component Side w8: v1@560,1135.28 v1(560,1140)
  Component Side w10: v1(560,1140) 565,1140 586.54,1118.46 U2.16@586.54,1108.74 ; v1(745,978.46) 782.13,1015.59 Q1.1@788.5,1015.59
  Solder Side w10: v1(560,1140) 565,1140 607.01,1097.99 625.47,1097.99 v1(745,978.46)
NetQ1_2: Q1.2 R7.2 | length 75.4
  Component Side w25: 785,955 cw(c781.39,951.39) 786.5,951.39 R7.2@786.5,880
NetQ2_1: Q2.1 Q3.2 R21.2 | length 392.1
  Component Side w12: Q3.2@1490.59,1078.5 1603.5,1078.5 1625,1100 1625,1215 1625.59,1215.59 Q2.1@1653.5,1215.59 1652.09,1217.01 R21.2@1652.09,1320
NetQ2_2: Q2.2 R22.2 | length 347.1
  Component Side w10: R22.2@1455,1273.5 1479.76,1273.5 1498.27,1255 v1(1610,1255) ; v1(1653.5,1126.5) Q2.2@1653.5,1164.41
  Solder Side w10: v1(1610,1255) 1653.5,1211.5 v1(1653.5,1126.5)
NetQ2_3: Q2.3 Q3.1 R20.1 | length 673.4
  Component Side w8: R20.1@1248.5,1215 1248.5,1186.5 1356.5,1078.5 Q3.1@1439.41,1078.5 1462.91,1055 1695,1055 1716.5,1076.5 Q2.3@1716.5,1190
